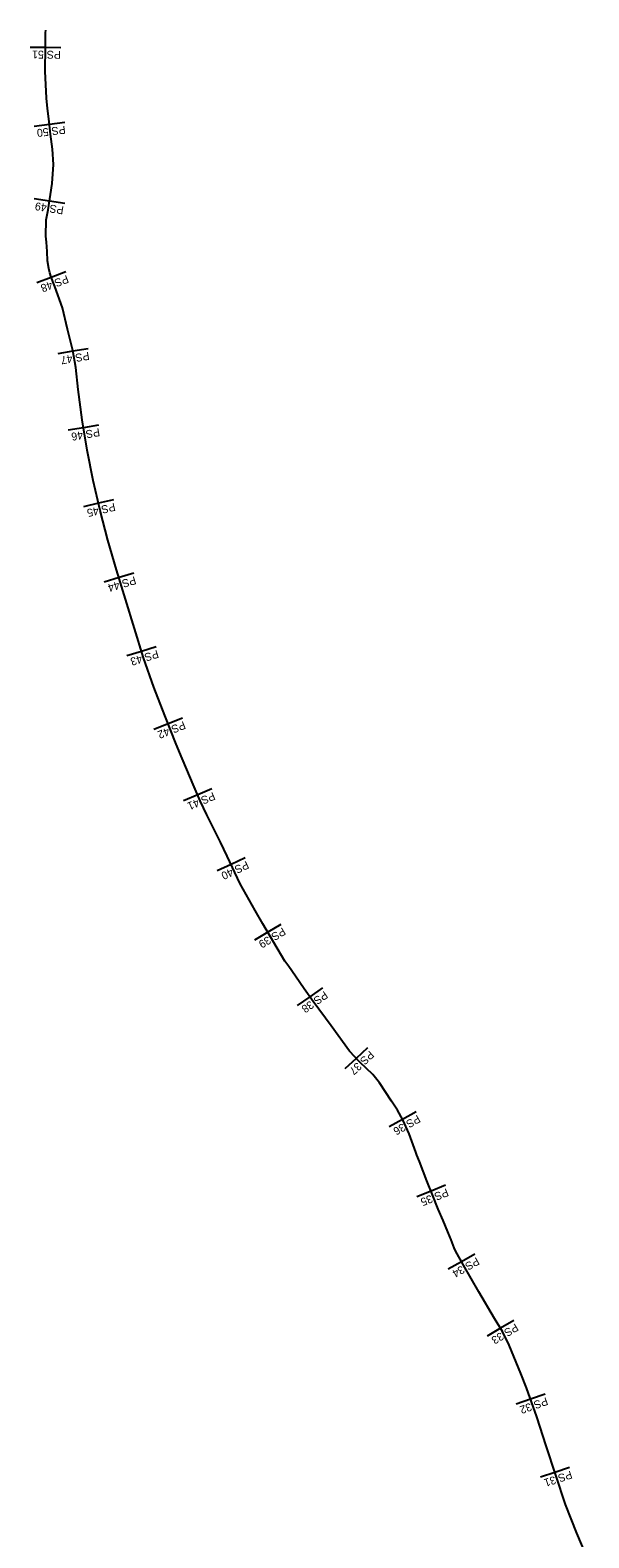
# Model space of a CAD drawing. Extents: x -844670 to -843025, y -997533 to -995513.
# Drawn here: x -844670 to -844308, y -996514 to -995537 of the extents above; entities that cross this region are included whole.
import ezdxf

# ---------------------------------------------------------------- set-up
doc = ezdxf.new("R2010")
doc.units = 0
doc.layers.add('Osa', color=7, linetype='Continuous')
doc.layers.add('Řezy', color=7, linetype='Continuous')

msp = doc.modelspace()

# ---------------------------------------------------------------- linework, layer by layer
at = {"layer": 'Osa'}
msp.add_lwpolyline([(-844307.53, -996529.45), (-844315.28, -996511.19), (-844322.67, -996492.59), (-844328.88, -996473.55), (-844335.12, -996454.52), (-844341.27, -996435.66), (-844347.9, -996416.86), (-844351.59, -996407.65), (-844359.16, -996389.32), (-844363.58, -996380.39), (-844368.7, -996371.89), (-844378.84, -996354.73), (-844388.81, -996337.42), (-844394.06, -996328.1), (-844394.97, -996326.12), (-844396.92, -996320.9), (-844398.88, -996315.68), (-844402.03, -996308.35), (-844405.18, -996301.03), (-844408.86, -996291.84), (-844412.55, -996282.65), (-844417.33, -996270.21), (-844419.02, -996266.1), (-844419.68, -996264.06), (-844424.16, -996252.22), (-844428.23, -996243.08), (-844431.66, -996236.96), (-844435.62, -996230.94), (-844443.38, -996219.18), (-844447.67, -996213.72), (-844456.06, -996205.86), (-844462.83, -996198.61), (-844474.72, -996182.3), (-844486.42, -996166.33), (-844492.1, -996158.12), (-844497.79, -996149.92), (-844502.08, -996143.79), (-844504.68, -996140.23), (-844511.85, -996128.18), (-844519.03, -996116.12), (-844523.94, -996107.43), (-844533.59, -996090.08), (-844542.04, -996072.11), (-844546.43, -996063.18), (-844555.21, -996045.31), (-844559.6, -996036.37), (-844563.49, -996027.16), (-844571.24, -996008.81), (-844575.08, -995999.67), (-844582.54, -995981.02), (-844589.66, -995962.57), (-844596.31, -995943.69), (-844602.17, -995924.63), (-844608.08, -995905.52), (-844613.78, -995886.51), (-844619.57, -995867.42), (-844624.4, -995848.01), (-844628.94, -995828.61), (-844632.81, -995809.03), (-844636.18, -995789.38), (-844638.7, -995769.62), (-844640.32, -995755.44), (-844642.17, -995744.41), (-844645.58, -995730.56), (-844648.99, -995716.71), (-844653.94, -995702.86), (-844656.26, -995696.8), (-844657.01, -995694), (-844657.76, -995691.21), (-844658.62, -995686.27), (-844658.9, -995680.2), (-844659.19, -995674.14), (-844659.71, -995670.33), (-844659.53, -995659.64), (-844658.23, -995653.07), (-844655.56, -995636.12), (-844654.74, -995623.74), (-844655.42, -995613.92), (-844656.62, -995604.08), (-844657.83, -995594.25), (-844658.53, -995587.5), (-844659.23, -995580.74), (-844660.07, -995563.3), (-844659.88, -995547.71), (-844659.82, -995540.9), (-844659.9, -995538.36), (-844659.78, -995536.68)], dxfattribs=at)
at = {"layer": 'Řezy'}
for points in [[(-844649.88, -995548.07), (-844659.88, -995547.94), (-844669.88, -995547.82)], [(-844647.47, -995596.6), (-844657.39, -995597.82), (-844667.32, -995599.04)], [(-844647.48, -995649.07), (-844657.36, -995647.51), (-844667.23, -995645.95)], [(-844646.84, -995693.42), (-844656.18, -995696.98), (-844665.53, -995700.54)], [(-844632.22, -995743.22), (-844642.09, -995744.87), (-844651.95, -995746.52)], [(-844625.46, -995792.71), (-844635.32, -995794.4), (-844645.17, -995796.09)], [(-844615.74, -995841.13), (-844625.47, -995843.41), (-844635.21, -995845.69)], [(-844602.67, -995888.74), (-844612.25, -995891.61), (-844621.83, -995894.48)], [(-844588.06, -995936.48), (-844597.62, -995939.42), (-844607.18, -995942.36)], [(-844571.12, -995982.64), (-844580.4, -995986.35), (-844589.69, -995990.06)], [(-844552.02, -996028.63), (-844561.23, -996032.52), (-844570.44, -996036.42)], [(-844530.43, -996073.29), (-844539.49, -996077.54), (-844548.54, -996081.79)], [(-844507.21, -996116.43), (-844515.8, -996121.54), (-844524.39, -996126.66)], [(-844480.25, -996157.67), (-844488.47, -996163.37), (-844496.69, -996169.06)], [(-844451.14, -996196.48), (-844458.45, -996203.3), (-844465.76, -996210.13)], [(-844419.63, -996237.96), (-844428.35, -996242.86), (-844437.07, -996247.75)], [(-844400.6, -996285.58), (-844409.88, -996289.3), (-844419.16, -996293.02)], [(-844381.38, -996330.24), (-844390.09, -996335.15), (-844398.8, -996340.06)], [(-844356.27, -996373.15), (-844364.84, -996378.3), (-844373.41, -996383.45)], [(-844335.86, -996420.93), (-844345.29, -996424.26), (-844354.72, -996427.58)], [(-844319.98, -996468.57), (-844329.49, -996471.69), (-844338.99, -996474.81)]]:
    msp.add_lwpolyline(points, dxfattribs=at)

# ---------------------------------------------------------------- texts
for s, rotation, p in [('PS 51', 179.30198, (-844649.91, -995550.12)), ('PS 50', 186.99951, (-844647.22, -995598.64)), ('PS 49', 171.01261, (-844647.8, -995651.1)), ('PS 48', 200.87604, (-844646.11, -995695.33)), ('PS 47', 189.49601, (-844631.89, -995745.25)), ('PS 46', 189.73162, (-844625.12, -995794.73)), ('PS 45', 193.18536, (-844615.27, -995843.13)), ('PS 44', 196.67712, (-844602.08, -995890.71)), ('PS 43', 197.09428, (-844587.46, -995938.44)), ('PS 42', 201.76963, (-844570.36, -995984.55)), ('PS 41', 202.92398, (-844551.22, -996030.52)), ('PS 40', 205.16425, (-844529.56, -996075.15)), ('PS 39', 210.76063, (-844506.16, -996118.19)), ('PS 38', 214.71693, (-844479.08, -996159.36)), ('PS 37', 223.03914, (-844449.74, -996197.98)), ('PS 36', 209.28876, (-844418.63, -996239.75)), ('PS 35', 201.83096, (-844399.83, -996287.49)), ('PS 34', 209.41101, (-844380.37, -996332.02)), ('PS 33', 211.01329, (-844355.21, -996374.91)), ('PS 32', 199.42569, (-844335.18, -996422.87)), ('PS 31', 198.17721, (-844319.34, -996470.52))]:
    msp.add_text(s, height=5.132, rotation=rotation, dxfattribs=at).set_placement(p)

doc.saveas('drawing.dxf')
